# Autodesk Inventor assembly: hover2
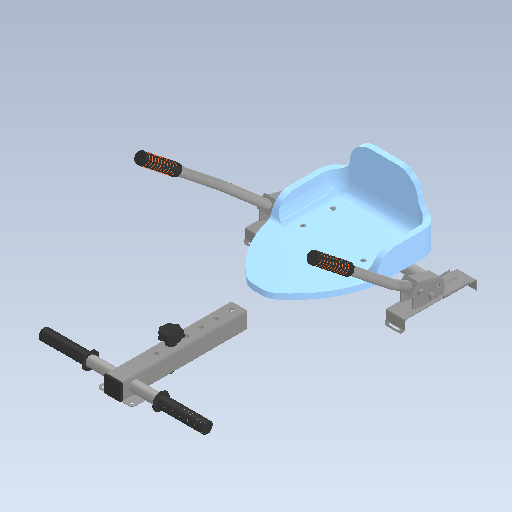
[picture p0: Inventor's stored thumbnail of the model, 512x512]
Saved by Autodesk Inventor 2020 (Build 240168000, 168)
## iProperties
Company: UNSPECIFIED
Created: 1900-01
Part Number: hover2
Description: STEP AP203
Document SubType Name: Assembly
Designer: bruno
Sending System: ASCON Math Kernel
Preprocessor: ASCON STEP Converter 1.3
Title: Òåëåæêà
Author: UNSPECIFIED
Revision Number: ANYUNSPECIFIED
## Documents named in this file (18)
- C:\Users\bruno\Documents\1-Cours-2022-23\1SI\2. Cinématique\Hoverboard\Inventor-Hoverboard\hover2.iam
- C:\Users\bruno\Documents\1-Cours-2022-23\1SI\2. Cinématique\Hoverboard\Inventor-Hoverboard\Tube-2.ipt
- C:\Users\bruno\Documents\1-Cours-2022-23\1SI\2. Cinématique\Hoverboard\Inventor-Hoverboard\Tube-carre.ipt
- C:\Users\bruno\Documents\1-Cours-2022-23\1SI\2. Cinématique\Hoverboard\Inventor-Hoverboard\Plat-1.ipt
- C:\Users\bruno\Documents\1-Cours-2022-23\1SI\2. Cinématique\Hoverboard\Inventor-Hoverboard\Tube-1.ipt
- C:\Users\bruno\Documents\1-Cours-2022-23\1SI\2. Cinématique\Hoverboard\Inventor-Hoverboard\Plat-2.ipt
- C:\Users\bruno\Documents\1-Cours-2022-23\1SI\2. Cinématique\Hoverboard\Inventor-Hoverboard\Ecrou.ipt
- C:\Users\bruno\Documents\1-Cours-2022-23\1SI\2. Cinématique\Hoverboard\Inventor-Hoverboard\Axe-1.iam
- C:\Users\bruno\Documents\1-Cours-2022-23\1SI\2. Cinématique\Hoverboard\Inventor-Hoverboard\Rondelle.ipt
- C:\Users\bruno\Documents\1-Cours-2022-23\1SI\2. Cinématique\Hoverboard\Inventor-Hoverboard\HANDLE GRIP.ipt
- C:\Users\bruno\Documents\1-Cours-2022-23\1SI\2. Cinématique\Hoverboard\Inventor-Hoverboard\Articulation.iam
- C:\Users\bruno\Documents\1-Cours-2022-23\1SI\2. Cinématique\Hoverboard\Inventor-Hoverboard\Rondelle-10450-78.ipt
- C:\Users\bruno\Documents\1-Cours-2022-23\1SI\2. Cinématique\Hoverboard\Inventor-Hoverboard\Poignee-1.iam
- C:\Users\bruno\Documents\1-Cours-2022-23\1SI\2. Cinématique\Hoverboard\Inventor-Hoverboard\Tenon.ipt
- C:\Users\bruno\Documents\1-Cours-2022-23\1SI\2. Cinématique\Hoverboard\Inventor-Hoverboard\Screw_Knob.ipt
- C:\Users\bruno\Documents\1-Cours-2022-23\1SI\2. Cinématique\Hoverboard\Inventor-Hoverboard\TUBE CAP 40x40.ipt
- C:\Users\bruno\Documents\1-Cours-2022-23\1SI\2. Cinématique\Hoverboard\Inventor-Hoverboard\TUBE CAP 40x40_1.ipt
- C:\Users\bruno\Documents\1-Cours-2022-23\1SI\2. Cinématique\Hoverboard\Inventor-Hoverboard\Siege.ipt
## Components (38 placed, 38 different names)
1. 2
2. 3
3. 4
4. 5
5. 6
6. 8
7. 10 [sub-assembly]
8. 11 [sub-assembly]
9. 12
10. 13
11. 14
12. 21 [sub-assembly]
13. 22
14. 23
15. 24
16. 28 [sub-assembly]
17. 29
18. 30 [sub-assembly]
19. 31
20. 32
21. 33
22. 37 [sub-assembly]
23. 38
24. 39
25. 40
26. 41
27. 42
28. 43
29. 44
30. 45
31. 46
32. 47
33. 48
34. 49
35. 50
36. 51
37. 52
38. 53
